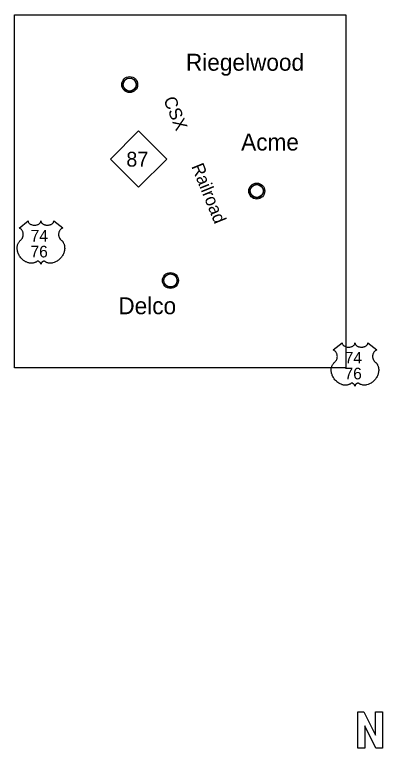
# Model space of a CAD drawing. Extents: x 5197761 to 5514561, y 1890130 to 2080942.
# Drawn here: x 5458936 to 5476337, y 1985842 to 2020541 of the extents above; entities that cross this region are included whole.
import ezdxf

# ---------------------------------------------------------------- set-up
doc = ezdxf.new("R2010")
doc.units = 0
for name, color, linetype in [('Exist Civil Demographics Community CELL', 7, 'Continuous'), ('Exist Civil Demographics Community Label', 7, 'Continuous'), ('Exist Railroad Mainline Label', 7, 'Continuous'), ('Exist Road Primary NC Shield CELL', 7, 'Continuous'), ('Exist Road Primary NC Shield Number Label', 7, 'Continuous'), ('Exist Road Primary US Shield CELL', 7, 'Continuous'), ('Exist Road Primary US Shield Number Label', 7, 'Continuous'), ('Map Preparation Inset Cut Line', 7, 'Continuous'), ('Map Preparation North Arrow CELL', 7, 'Continuous')]:
    doc.layers.add(name, color=color, linetype=linetype)

msp = doc.modelspace()

# ---------------------------------------------------------------- linework, layer by layer
at = {"layer": 'Exist Civil Demographics Community CELL'}
for points in [[(5464069, 2017284), (5464073, 2017306), (5464080, 2017332), (5464092, 2017361), (5464104, 2017384), (5464117, 2017407), (5464132, 2017427), (5464148, 2017445), (5464166, 2017463), (5464188, 2017482), (5464210, 2017496), (5464230, 2017508), (5464250, 2017518), (5464272, 2017527), (5464294, 2017534), (5464311, 2017539), (5464331, 2017542), (5464347, 2017544), (5464373, 2017545), (5464391, 2017545), (5464413, 2017544), (5464433, 2017541), (5464452, 2017537), (5464472, 2017532), (5464493, 2017524), (5464520, 2017512), (5464545, 2017498), (5464565, 2017484), (5464586, 2017468), (5464599, 2017455), (5464615, 2017438), (5464631, 2017419), (5464643, 2017401), (5464656, 2017381), (5464666, 2017360), (5464674, 2017340), (5464680, 2017320), (5464685, 2017302), (5464689, 2017277), (5464692, 2017259), (5464693, 2017235), (5464692, 2017211), (5464690, 2017189), (5464686, 2017167), (5464680, 2017142), (5464672, 2017119), (5464663, 2017098), (5464650, 2017074), (5464637, 2017053), (5464623, 2017034), (5464606, 2017015), (5464585, 2016996), (5464565, 2016979), (5464545, 2016965), (5464528, 2016955), (5464501, 2016942), (5464472, 2016931), (5464448, 2016926), (5464422, 2016920), (5464404, 2016919), (5464386, 2016917), (5464364, 2016917), (5464347, 2016919), (5464324, 2016922), (5464300, 2016927), (5464282, 2016932), (5464261, 2016940), (5464243, 2016948), (5464227, 2016957), (5464200, 2016973), (5464178, 2016990), (5464158, 2017008), (5464140, 2017028), (5464128, 2017044), (5464116, 2017060), (5464099, 2017089), (5464092, 2017103), (5464086, 2017119), (5464075, 2017152), (5464069, 2017180), (5464066, 2017200), (5464065, 2017226), (5464065, 2017245), (5464067, 2017270)], [(5470082, 2012250), (5470086, 2012272), (5470093, 2012298), (5470105, 2012327), (5470117, 2012350), (5470130, 2012373), (5470145, 2012393), (5470161, 2012411), (5470179, 2012429), (5470202, 2012448), (5470223, 2012462), (5470243, 2012474), (5470263, 2012484), (5470285, 2012493), (5470307, 2012500), (5470325, 2012505), (5470344, 2012508), (5470361, 2012510), (5470386, 2012511), (5470404, 2012511), (5470426, 2012510), (5470446, 2012507), (5470466, 2012503), (5470486, 2012497), (5470506, 2012490), (5470533, 2012478), (5470558, 2012464), (5470578, 2012450), (5470599, 2012434), (5470612, 2012421), (5470629, 2012404), (5470644, 2012385), (5470656, 2012367), (5470669, 2012347), (5470679, 2012326), (5470687, 2012306), (5470693, 2012286), (5470698, 2012267), (5470703, 2012243), (5470705, 2012224), (5470706, 2012200), (5470706, 2012177), (5470703, 2012155), (5470699, 2012133), (5470693, 2012108), (5470685, 2012085), (5470676, 2012064), (5470664, 2012040), (5470650, 2012019), (5470637, 2012000), (5470620, 2011981), (5470599, 2011962), (5470579, 2011945), (5470559, 2011931), (5470541, 2011921), (5470514, 2011908), (5470485, 2011897), (5470462, 2011892), (5470435, 2011886), (5470417, 2011884), (5470399, 2011883), (5470377, 2011883), (5470360, 2011885), (5470337, 2011888), (5470314, 2011893), (5470295, 2011898), (5470275, 2011906), (5470256, 2011914), (5470241, 2011923), (5470214, 2011939), (5470191, 2011956), (5470172, 2011974), (5470154, 2011994), (5470141, 2012010), (5470129, 2012026), (5470113, 2012055), (5470106, 2012069), (5470099, 2012085), (5470089, 2012118), (5470082, 2012146), (5470080, 2012166), (5470078, 2012192), (5470078, 2012211), (5470080, 2012236)], [(5465999, 2008018), (5466003, 2008040), (5466010, 2008066), (5466022, 2008095), (5466033, 2008118), (5466047, 2008141), (5466062, 2008162), (5466078, 2008179), (5466096, 2008197), (5466118, 2008216), (5466140, 2008230), (5466159, 2008242), (5466180, 2008252), (5466201, 2008261), (5466224, 2008268), (5466241, 2008273), (5466261, 2008276), (5466277, 2008279), (5466303, 2008280), (5466320, 2008279), (5466343, 2008278), (5466363, 2008275), (5466382, 2008271), (5466402, 2008266), (5466423, 2008258), (5466449, 2008246), (5466475, 2008232), (5466495, 2008218), (5466515, 2008202), (5466529, 2008190), (5466545, 2008172), (5466561, 2008153), (5466573, 2008135), (5466585, 2008115), (5466595, 2008094), (5466603, 2008074), (5466610, 2008054), (5466615, 2008036), (5466619, 2008011), (5466622, 2007993), (5466623, 2007969), (5466622, 2007946), (5466620, 2007923), (5466616, 2007901), (5466609, 2007876), (5466602, 2007853), (5466593, 2007833), (5466580, 2007809), (5466567, 2007787), (5466553, 2007769), (5466536, 2007750), (5466515, 2007730), (5466495, 2007713), (5466475, 2007699), (5466458, 2007689), (5466430, 2007677), (5466402, 2007666), (5466378, 2007660), (5466352, 2007655), (5466334, 2007653), (5466316, 2007652), (5466294, 2007652), (5466276, 2007653), (5466254, 2007656), (5466230, 2007661), (5466212, 2007667), (5466191, 2007674), (5466173, 2007682), (5466157, 2007691), (5466130, 2007707), (5466108, 2007725), (5466088, 2007742), (5466070, 2007762), (5466057, 2007778), (5466046, 2007794), (5466029, 2007823), (5466022, 2007837), (5466015, 2007853), (5466005, 2007886), (5465999, 2007914), (5465996, 2007935), (5465995, 2007960), (5465995, 2007979), (5465997, 2008005)]]:
    msp.add_lwpolyline(points, close=True, dxfattribs=at)
for centre, radius in [((5464380, 2017234), 377), ((5464378, 2017235), 307), ((5470393, 2012200), 377), ((5470392, 2012201), 307), ((5466309, 2007968), 377), ((5466308, 2007969), 307)]:
    msp.add_circle(centre, radius, dxfattribs=at)
at = {"layer": 'Exist Road Primary NC Shield CELL'}
msp.add_lwpolyline([(5463472, 2013714), (5464804, 2015046), (5466136, 2013714), (5464804, 2012382)], close=True, dxfattribs=at)
at = {"layer": 'Exist Road Primary US Shield CELL'}
for points in [[(5459571, 2010789), (5459572, 2010772), (5459576, 2010751), (5459579, 2010740), (5459589, 2010719), (5459605, 2010695), (5459628, 2010671), (5459653, 2010650), (5459670, 2010639), (5459699, 2010624), (5459732, 2010610), (5459769, 2010599), (5459806, 2010592), (5459847, 2010587), (5459887, 2010586), (5459931, 2010590), (5459979, 2010599), (5460002, 2010605), (5460026, 2010613), (5460049, 2010623), (5460075, 2010636), (5460095, 2010650), (5460111, 2010661), (5460134, 2010683), (5460152, 2010705), (5460159, 2010718), (5460166, 2010730), (5460175, 2010755), (5460177, 2010767), (5460179, 2010790), (5460180, 2010770), (5460182, 2010758), (5460186, 2010746), (5460191, 2010733), (5460200, 2010715), (5460210, 2010700), (5460229, 2010678), (5460241, 2010667), (5460251, 2010658), (5460280, 2010638), (5460314, 2010621), (5460331, 2010614), (5460348, 2010608), (5460369, 2010601), (5460392, 2010596), (5460414, 2010592), (5460436, 2010589), (5460459, 2010587), (5460478, 2010586), (5460501, 2010587), (5460523, 2010588), (5460544, 2010590), (5460569, 2010594), (5460588, 2010599), (5460614, 2010606), (5460637, 2010614), (5460657, 2010623), (5460683, 2010636), (5460705, 2010650), (5460720, 2010662), (5460739, 2010679), (5460756, 2010700), (5460767, 2010715), (5460774, 2010730), (5460781, 2010746), (5460785, 2010763), (5460787, 2010778), (5460787, 2010791), (5461212, 2010452), (5461202, 2010448), (5461179, 2010437), (5461161, 2010426), (5461132, 2010405), (5461119, 2010394), (5461107, 2010382), (5461095, 2010370), (5461085, 2010358), (5461073, 2010341), (5461062, 2010324), (5461051, 2010305), (5461043, 2010289), (5461030, 2010254), (5461024, 2010233), (5461019, 2010214), (5461014, 2010177), (5461013, 2010158), (5461013, 2010141), (5461014, 2010122), (5461016, 2010104), (5461019, 2010085), (5461022, 2010068), (5461028, 2010048), (5461035, 2010024), (5461044, 2010001), (5461064, 2009964), (5461089, 2009927), (5461107, 2009906), (5461124, 2009888), (5461150, 2009866), (5461165, 2009853), (5461181, 2009837), (5461208, 2009806), (5461218, 2009791), (5461229, 2009775), (5461239, 2009758), (5461249, 2009740), (5461257, 2009724), (5461272, 2009688), (5461283, 2009652), (5461288, 2009634), (5461296, 2009592), (5461299, 2009571), (5461302, 2009531), (5461303, 2009481), (5461299, 2009435), (5461290, 2009380), (5461283, 2009348), (5461272, 2009310), (5461261, 2009277), (5461241, 2009228), (5461224, 2009193), (5461202, 2009152), (5461186, 2009127), (5461169, 2009100), (5461146, 2009070), (5461120, 2009037), (5461089, 2009003), (5461063, 2008977), (5461030, 2008948), (5461010, 2008931), (5460982, 2008909), (5460942, 2008883), (5460904, 2008861), (5460871, 2008844), (5460842, 2008832), (5460804, 2008817), (5460741, 2008800), (5460718, 2008795), (5460691, 2008791), (5460666, 2008789), (5460641, 2008787), (5460608, 2008787), (5460575, 2008790), (5460544, 2008794), (5460512, 2008801), (5460478, 2008811), (5460447, 2008823), (5460416, 2008838), (5460363, 2008872), (5460348, 2008880), (5460340, 2008882), (5460319, 2008883), (5460300, 2008879), (5460281, 2008871), (5460269, 2008865), (5460253, 2008854), (5460241, 2008845), (5460227, 2008831), (5460217, 2008820), (5460209, 2008810), (5460194, 2008787), (5460189, 2008776), (5460183, 2008762), (5460178, 2008741), (5460172, 2008767), (5460164, 2008785), (5460155, 2008800), (5460146, 2008813), (5460131, 2008830), (5460117, 2008843), (5460101, 2008856), (5460084, 2008867), (5460071, 2008874), (5460058, 2008878), (5460043, 2008882), (5460030, 2008883), (5460020, 2008883), (5460006, 2008880), (5459986, 2008866), (5459968, 2008853), (5459948, 2008841), (5459925, 2008828), (5459908, 2008820), (5459887, 2008812), (5459863, 2008804), (5459837, 2008797), (5459810, 2008792), (5459786, 2008788), (5459761, 2008786), (5459738, 2008785), (5459714, 2008786), (5459692, 2008787), (5459666, 2008790), (5459634, 2008794), (5459607, 2008800), (5459579, 2008808), (5459550, 2008817), (5459519, 2008829), (5459481, 2008846), (5459454, 2008859), (5459411, 2008884), (5459362, 2008918), (5459324, 2008949), (5459297, 2008974), (5459256, 2009015), (5459233, 2009042), (5459195, 2009090), (5459171, 2009125), (5459156, 2009150), (5459133, 2009192), (5459121, 2009217), (5459105, 2009255), (5459092, 2009290), (5459082, 2009322), (5459076, 2009343), (5459068, 2009379), (5459063, 2009405), (5459058, 2009441), (5459056, 2009478), (5459055, 2009513), (5459056, 2009541), (5459059, 2009575), (5459065, 2009610), (5459072, 2009640), (5459078, 2009662), (5459087, 2009689), (5459099, 2009718), (5459113, 2009746), (5459126, 2009770), (5459143, 2009795), (5459160, 2009816), (5459181, 2009840), (5459204, 2009861), (5459225, 2009878), (5459249, 2009902), (5459262, 2009917), (5459278, 2009937), (5459290, 2009956), (5459300, 2009973), (5459313, 2009998), (5459320, 2010016), (5459330, 2010045), (5459335, 2010065), (5459340, 2010091), (5459343, 2010115), (5459345, 2010146), (5459344, 2010171), (5459341, 2010200), (5459335, 2010228), (5459328, 2010253), (5459318, 2010281), (5459308, 2010302), (5459292, 2010330), (5459274, 2010356), (5459255, 2010377), (5459236, 2010396), (5459218, 2010410), (5459201, 2010422), (5459179, 2010435), (5459159, 2010445), (5459146, 2010451)], [(5474434, 2005021), (5474435, 2005003), (5474439, 2004982), (5474442, 2004971), (5474452, 2004951), (5474468, 2004927), (5474491, 2004903), (5474516, 2004882), (5474533, 2004871), (5474562, 2004855), (5474595, 2004841), (5474632, 2004831), (5474669, 2004823), (5474710, 2004819), (5474750, 2004818), (5474794, 2004821), (5474842, 2004831), (5474865, 2004836), (5474889, 2004845), (5474912, 2004854), (5474938, 2004868), (5474958, 2004881), (5474974, 2004893), (5474997, 2004914), (5475015, 2004937), (5475022, 2004949), (5475029, 2004961), (5475038, 2004987), (5475040, 2004998), (5475042, 2005022), (5475043, 2005002), (5475045, 2004990), (5475049, 2004978), (5475054, 2004965), (5475063, 2004947), (5475073, 2004932), (5475092, 2004909), (5475104, 2004898), (5475114, 2004889), (5475143, 2004869), (5475177, 2004852), (5475194, 2004845), (5475211, 2004839), (5475232, 2004833), (5475255, 2004827), (5475277, 2004824), (5475299, 2004820), (5475322, 2004819), (5475341, 2004818), (5475364, 2004818), (5475386, 2004820), (5475407, 2004822), (5475432, 2004826), (5475451, 2004830), (5475476, 2004837), (5475500, 2004845), (5475520, 2004854), (5475546, 2004868), (5475568, 2004881), (5475583, 2004894), (5475602, 2004911), (5475619, 2004931), (5475630, 2004946), (5475637, 2004961), (5475644, 2004978), (5475648, 2004995), (5475650, 2005009), (5475650, 2005022), (5476075, 2004683), (5476065, 2004680), (5476042, 2004668), (5476024, 2004657), (5475995, 2004637), (5475982, 2004626), (5475970, 2004614), (5475958, 2004601), (5475948, 2004589), (5475936, 2004572), (5475925, 2004555), (5475914, 2004536), (5475906, 2004520), (5475893, 2004486), (5475886, 2004464), (5475882, 2004446), (5475877, 2004408), (5475876, 2004390), (5475876, 2004372), (5475877, 2004353), (5475879, 2004335), (5475882, 2004316), (5475885, 2004300), (5475890, 2004279), (5475898, 2004256), (5475907, 2004233), (5475927, 2004196), (5475952, 2004158), (5475970, 2004137), (5475987, 2004119), (5476013, 2004097), (5476028, 2004085), (5476044, 2004068), (5476070, 2004037), (5476081, 2004023), (5476092, 2004006), (5476102, 2003990), (5476112, 2003971), (5476120, 2003956), (5476135, 2003919), (5476146, 2003884), (5476151, 2003865), (5476159, 2003824), (5476162, 2003803), (5476165, 2003762), (5476166, 2003713), (5476162, 2003666), (5476153, 2003612), (5476146, 2003579), (5476135, 2003541), (5476124, 2003508), (5476104, 2003460), (5476087, 2003425), (5476065, 2003383), (5476049, 2003359), (5476032, 2003332), (5476009, 2003301), (5475983, 2003269), (5475952, 2003234), (5475926, 2003209), (5475893, 2003179), (5475873, 2003163), (5475845, 2003141), (5475805, 2003115), (5475767, 2003093), (5475734, 2003076), (5475705, 2003063), (5475667, 2003049), (5475604, 2003031), (5475581, 2003027), (5475554, 2003023), (5475529, 2003020), (5475504, 2003019), (5475471, 2003019), (5475438, 2003021), (5475407, 2003026), (5475375, 2003032), (5475341, 2003043), (5475310, 2003055), (5475279, 2003070), (5475226, 2003103), (5475211, 2003111), (5475203, 2003113), (5475182, 2003114), (5475163, 2003110), (5475144, 2003103), (5475132, 2003096), (5475116, 2003086), (5475104, 2003076), (5475090, 2003063), (5475080, 2003051), (5475072, 2003042), (5475057, 2003019), (5475052, 2003008), (5475046, 2002993), (5475041, 2002972), (5475035, 2002999), (5475027, 2003016), (5475018, 2003031), (5475008, 2003045), (5474994, 2003062), (5474980, 2003075), (5474964, 2003088), (5474947, 2003098), (5474934, 2003105), (5474921, 2003110), (5474906, 2003114), (5474893, 2003115), (5474883, 2003114), (5474869, 2003111), (5474849, 2003097), (5474831, 2003085), (5474811, 2003072), (5474788, 2003060), (5474770, 2003052), (5474750, 2003044), (5474726, 2003036), (5474700, 2003029), (5474673, 2003024), (5474649, 2003020), (5474624, 2003018), (5474601, 2003017), (5474577, 2003017), (5474555, 2003019), (5474529, 2003021), (5474497, 2003026), (5474470, 2003032), (5474442, 2003040), (5474413, 2003049), (5474382, 2003060), (5474344, 2003077), (5474317, 2003091), (5474274, 2003115), (5474225, 2003150), (5474187, 2003180), (5474160, 2003205), (5474119, 2003246), (5474096, 2003273), (5474058, 2003321), (5474034, 2003356), (5474019, 2003382), (5473996, 2003423), (5473984, 2003449), (5473968, 2003487), (5473955, 2003521), (5473945, 2003554), (5473939, 2003575), (5473931, 2003611), (5473926, 2003637), (5473921, 2003672), (5473919, 2003710), (5473918, 2003744), (5473919, 2003773), (5473922, 2003806), (5473928, 2003842), (5473935, 2003872), (5473941, 2003894), (5473950, 2003920), (5473962, 2003950), (5473976, 2003978), (5473989, 2004001), (5474006, 2004026), (5474023, 2004048), (5474044, 2004071), (5474067, 2004093), (5474088, 2004110), (5474112, 2004134), (5474125, 2004149), (5474141, 2004169), (5474153, 2004188), (5474163, 2004205), (5474176, 2004229), (5474183, 2004248), (5474193, 2004277), (5474198, 2004297), (5474203, 2004323), (5474206, 2004347), (5474208, 2004377), (5474207, 2004403), (5474204, 2004432), (5474198, 2004460), (5474191, 2004485), (5474181, 2004513), (5474171, 2004533), (5474155, 2004561), (5474137, 2004587), (5474118, 2004608), (5474099, 2004627), (5474081, 2004641), (5474064, 2004653), (5474042, 2004667), (5474022, 2004677), (5474008, 2004682)]]:
    msp.add_lwpolyline(points, close=True, dxfattribs=at)
at = {"layer": 'Map Preparation Inset Cut Line'}
msp.add_lwpolyline([(5458936, 2020541), (5474602, 2020541), (5474602, 2003836), (5458936, 2003836)], close=True, dxfattribs=at)
at = {"layer": 'Map Preparation North Arrow CELL'}
msp.add_lwpolyline([(5475174, 1985842), (5475174, 1987569), (5475457, 1987569), (5476017, 1986462), (5476017, 1987561), (5476337, 1987561), (5476337, 1985850), (5476029, 1985850), (5475502, 1986912), (5475502, 1985842)], close=True, dxfattribs=at)

# ---------------------------------------------------------------- texts
at = {"layer": 'Exist Civil Demographics Community Label'}
for s, p in [('Riegelwood', (5467042, 2017891)), ('Acme', (5469655, 2014117)), ('Delco', (5463842, 2006373))]:
    msp.add_text(s, height=800, dxfattribs=at).set_placement(p)
at = {"layer": 'Exist Railroad Mainline Label'}
for s, rotation, p in [('CSX', 291.9957, (5465965, 2016529)), ('Railroad', 292.1302, (5467287, 2013368))]:
    msp.add_text(s, height=600, rotation=rotation, dxfattribs=at).set_placement(p)
at = {"layer": 'Exist Road Primary NC Shield Number Label'}
msp.add_text('87', height=700, dxfattribs=at).set_placement((5464221, 2013355))
at = {"layer": 'Exist Road Primary US Shield Number Label'}
for s, p in [('74', (5459694, 2009813)), ('76', (5459686, 2009061)), ('74', (5474557, 2004044)), ('76', (5474548, 2003293))]:
    msp.add_text(s, height=550, dxfattribs=at).set_placement(p)

doc.saveas('drawing.dxf')
